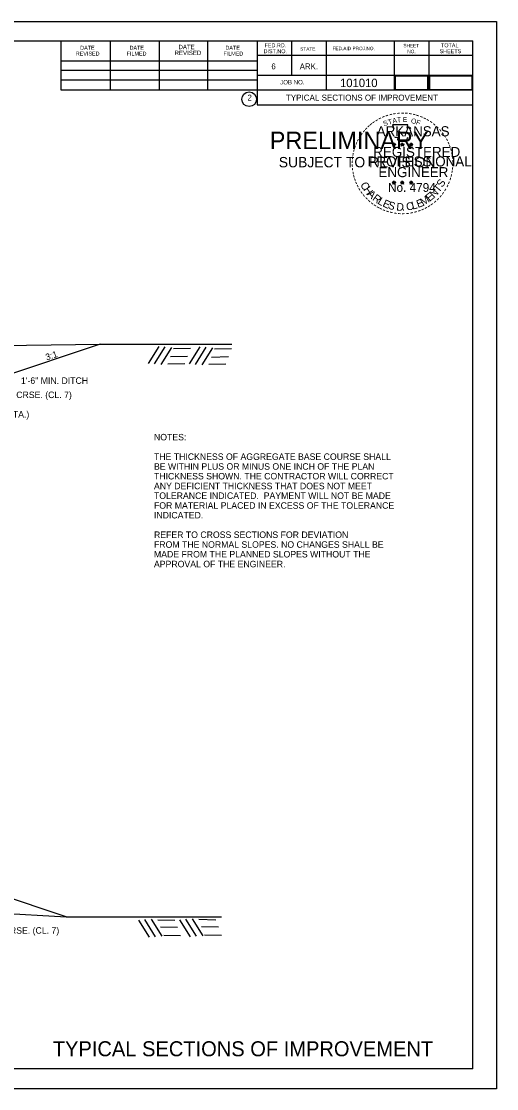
# Model space of a CAD drawing. Extents: x 1373719 to 1374161, y 379835 to 380167.
# Drawn here: x 1373998.9 to 1374046.4, y 379901.1 to 380007.8 of the extents above; entities that cross this region are included whole.
import ezdxf

# ---------------------------------------------------------------- set-up
doc = ezdxf.new("R2010")
doc.units = 0
for name, color, linetype in [('Agg Base Course Text', 7, 'Continuous'), ('DATE', 7, 'Continuous'), ('GREEN_TXT', 7, 'Continuous'), ('Ground Hatch', 7, 'Continuous'), ('Page Number', 7, 'Continuous'), ('R_Border Notes', 7, 'Continuous'), ('R_Border Prem', 7, 'Continuous'), ('R_NoPlot', 7, 'Continuous'), ('R_Stamp', 7, 'Continuous'), ('T_Drafting', 7, 'Continuous'), ('Total Pages', 7, 'Continuous')]:
    doc.layers.add(name, color=color, linetype=linetype)

msp = doc.modelspace()

# ---------------------------------------------------------------- linework, layer by layer
for p, q in [((1374006.82, 379975.49), (1373996.85, 379972.17)), ((1374003.43, 379918.28), (1373993.52, 379921.58))]:
    msp.add_line(p, q)
at = {"layer": 'DATE'}
for p, q in [((1373885.97, 380005.81), (1374044.06, 380005.81)), ((1374002.93, 380000.87), (1374002.93, 380005.81)), ((1374007.86, 380000.87), (1374007.86, 380005.71)), ((1374012.74, 380000.87), (1374012.74, 380005.71)), ((1374017.58, 380000.87), (1374017.58, 380005.71)), ((1374022.51, 380005.81), (1374022.51, 379999.41)), ((1374025.93, 380005.81), (1374025.93, 380002.34)), ((1374029.4, 380005.81), (1374029.4, 380000.87)), ((1374036.19, 380005.81), (1374036.19, 380000.87)), ((1374039.66, 380005.81), (1374039.66, 380000.87)), ((1374044.06, 379903.08), (1374044.06, 380005.81)), ((1374002.93, 380003.8), (1374022.51, 380003.8)), ((1374044.06, 380004.34), (1374022.51, 380004.34)), ((1374044.06, 380004.35), (1374044.06, 380004.35)), ((1374002.93, 380002.87), (1374022.51, 380002.87)), ((1374044.06, 380002.34), (1374022.51, 380002.34)), ((1374002.93, 380001.9), (1374022.51, 380001.9)), ((1374044.06, 380000.87), (1374002.93, 380000.87)), ((1374022.51, 379999.41), (1374044.06, 379999.41)), ((1374044.06, 379903.08), (1373885.97, 379903.08))]:
    msp.add_line(p, q, dxfattribs=at)
msp.add_circle((1374021.71, 379999.98), 0.733, dxfattribs=at)
at = {"layer": 'Ground Hatch'}
for p, q in [((1374011.66, 379973.57), (1374012.72, 379975.28)), ((1374012.26, 379973.52), (1374013.32, 379975.23)), ((1374012.92, 379973.47), (1374013.99, 379975.18)), ((1374014.16, 379975.06), (1374015.86, 379975.11)), ((1374015.75, 379973.53), (1374016.81, 379975.24)), ((1374016.35, 379973.48), (1374017.41, 379975.19)), ((1374017.02, 379973.44), (1374018.08, 379975.14)), ((1374018.25, 379975.03), (1374019.95, 379975.07)), ((1374013.59, 379973.53), (1374015.29, 379973.57)), ((1374013.86, 379974.25), (1374015.55, 379974.29)), ((1374017.68, 379973.49), (1374019.38, 379973.53)), ((1374017.95, 379974.21), (1374019.65, 379974.25)), ((1374011.93, 379918.03), (1374013, 379916.32)), ((1374015.35, 379918.02), (1374016.42, 379916.32)), ((1374016.02, 379918.07), (1374017.09, 379916.36)), ((1374016.69, 379918.02), (1374018.38, 379917.97)), ((1374010.66, 379917.94), (1374011.73, 379916.23)), ((1374011.26, 379917.99), (1374012.33, 379916.28)), ((1374012.59, 379917.98), (1374014.29, 379917.93)), ((1374012.86, 379917.26), (1374014.56, 379917.22)), ((1374014.75, 379917.97), (1374015.82, 379916.27)), ((1374016.95, 379917.3), (1374018.65, 379917.25)), ((1374013.17, 379916.44), (1374014.86, 379916.4)), ((1374017.26, 379916.48), (1374018.95, 379916.44))]:
    msp.add_line(p, q, dxfattribs=at)
at = {"layer": 'Page Number'}
msp.add_lwpolyline([(1374036.3, 380000.95), (1374039.56, 380000.95), (1374039.56, 380002.27), (1374036.3, 380002.27)], close=True, dxfattribs=at)
at = {"layer": 'R_NoPlot'}
msp.add_lwpolyline([(1373879.77, 380007.76), (1374046.44, 380007.76), (1374046.44, 379901.09), (1373879.77, 379901.09)], close=True, dxfattribs=at)
at = {"layer": 'R_Stamp'}
for p, q in [((1374036, 379995.49), (1374036.18, 379995.43)), ((1374036, 379995.49), (1374036.13, 379995.47)), ((1374036, 379995.49), (1374036.12, 379995.43)), ((1374036.07, 379995.28), (1374036.18, 379995.43)), ((1374036.07, 379995.28), (1374036.13, 379995.41)), ((1374036.07, 379995.28), (1374036.18, 379995.39)), ((1374036.18, 379995.62), (1374036.16, 379995.49)), ((1374036.18, 379995.43), (1374036.18, 379995.62)), ((1374036.18, 379995.62), (1374036.2, 379995.49)), ((1374036.35, 379995.49), (1374036.18, 379995.43)), ((1374036.28, 379995.28), (1374036.18, 379995.43)), ((1374036.28, 379995.28), (1374036.18, 379995.39)), ((1374036.35, 379995.49), (1374036.21, 379995.46)), ((1374036.28, 379995.28), (1374036.22, 379995.43)), ((1374036.35, 379995.49), (1374036.25, 379995.44)), ((1374036.84, 379995.49), (1374037.01, 379995.43)), ((1374036.84, 379995.49), (1374036.96, 379995.47)), ((1374036.84, 379995.49), (1374036.96, 379995.43)), ((1374036.9, 379995.28), (1374037.01, 379995.43)), ((1374036.9, 379995.28), (1374036.97, 379995.41)), ((1374036.9, 379995.28), (1374037.01, 379995.39)), ((1374037.01, 379995.62), (1374036.99, 379995.49)), ((1374037.01, 379995.43), (1374037.01, 379995.62)), ((1374037.01, 379995.62), (1374037.04, 379995.49)), ((1374037.19, 379995.49), (1374037.01, 379995.43)), ((1374037.12, 379995.28), (1374037.01, 379995.43)), ((1374037.12, 379995.28), (1374037.01, 379995.39)), ((1374037.19, 379995.49), (1374037.04, 379995.46)), ((1374037.12, 379995.28), (1374037.05, 379995.43)), ((1374037.19, 379995.49), (1374037.08, 379995.44)), ((1374037.72, 379995.48), (1374037.89, 379995.43)), ((1374037.72, 379995.48), (1374037.85, 379995.46)), ((1374037.72, 379995.48), (1374037.84, 379995.42)), ((1374037.79, 379995.28), (1374037.89, 379995.43)), ((1374037.79, 379995.28), (1374037.85, 379995.4)), ((1374037.79, 379995.28), (1374037.89, 379995.39)), ((1374037.89, 379995.61), (1374037.87, 379995.48)), ((1374037.89, 379995.43), (1374037.89, 379995.61)), ((1374037.89, 379995.61), (1374037.92, 379995.48)), ((1374038.07, 379995.48), (1374037.89, 379995.43)), ((1374038, 379995.28), (1374037.89, 379995.43)), ((1374038, 379995.28), (1374037.89, 379995.39)), ((1374038.07, 379995.48), (1374037.93, 379995.46)), ((1374038, 379995.28), (1374037.93, 379995.42)), ((1374038.07, 379995.48), (1374037.97, 379995.43)), ((1374036, 379991.7), (1374036.18, 379991.65)), ((1374036, 379991.7), (1374036.13, 379991.68)), ((1374036, 379991.7), (1374036.12, 379991.64)), ((1374036.07, 379991.5), (1374036.18, 379991.65)), ((1374036.07, 379991.5), (1374036.13, 379991.62)), ((1374036.07, 379991.5), (1374036.17, 379991.61)), ((1374036.18, 379991.83), (1374036.16, 379991.7)), ((1374036.28, 379991.5), (1374036.17, 379991.61)), ((1374036.18, 379991.65), (1374036.18, 379991.83)), ((1374036.18, 379991.83), (1374036.2, 379991.7)), ((1374036.35, 379991.7), (1374036.18, 379991.65)), ((1374036.28, 379991.5), (1374036.18, 379991.65)), ((1374036.35, 379991.7), (1374036.21, 379991.68)), ((1374036.28, 379991.5), (1374036.21, 379991.64)), ((1374036.35, 379991.7), (1374036.25, 379991.65)), ((1374036.84, 379991.7), (1374037.01, 379991.65)), ((1374036.84, 379991.7), (1374036.96, 379991.68)), ((1374036.84, 379991.7), (1374036.95, 379991.64)), ((1374036.9, 379991.5), (1374037.01, 379991.65)), ((1374036.9, 379991.5), (1374036.97, 379991.62)), ((1374036.9, 379991.5), (1374037.01, 379991.61)), ((1374037.01, 379991.83), (1374036.99, 379991.7)), ((1374037.01, 379991.65), (1374037.01, 379991.83)), ((1374037.01, 379991.83), (1374037.03, 379991.7)), ((1374037.18, 379991.7), (1374037.01, 379991.65)), ((1374037.12, 379991.5), (1374037.01, 379991.65)), ((1374037.12, 379991.5), (1374037.01, 379991.61)), ((1374037.18, 379991.7), (1374037.04, 379991.68)), ((1374037.12, 379991.5), (1374037.05, 379991.64)), ((1374037.18, 379991.7), (1374037.08, 379991.65)), ((1374037.72, 379991.7), (1374037.89, 379991.64)), ((1374037.72, 379991.7), (1374037.85, 379991.67)), ((1374037.72, 379991.7), (1374037.84, 379991.64)), ((1374037.79, 379991.49), (1374037.89, 379991.64)), ((1374037.79, 379991.49), (1374037.85, 379991.62)), ((1374037.79, 379991.49), (1374037.89, 379991.6)), ((1374037.89, 379991.82), (1374037.87, 379991.7)), ((1374037.89, 379991.64), (1374037.89, 379991.82)), ((1374037.89, 379991.82), (1374037.92, 379991.7)), ((1374038.07, 379991.7), (1374037.89, 379991.64)), ((1374038, 379991.49), (1374037.89, 379991.64)), ((1374038, 379991.49), (1374037.89, 379991.6)), ((1374038.07, 379991.7), (1374037.92, 379991.67)), ((1374038, 379991.49), (1374037.93, 379991.64)), ((1374038.07, 379991.7), (1374037.97, 379991.65))]:
    msp.add_line(p, q, dxfattribs=at)
for points in [[(1374036.02, 379997.43), (1374036.16, 379997.01)], [(1374037.78, 379996.97), (1374037.85, 379997.11), (1374037.51, 379997.1), (1374037.58, 379997.43), (1374036.02, 379997.43)], [(1374036.27, 379996.22), (1374036.27, 379996.17), (1374036.55, 379996.16), (1374036.52, 379995.93), (1374037.46, 379995.93), (1374037.56, 379996.19)], [(1374036.18, 379995.62), (1374036.28, 379995.28), (1374036, 379995.49), (1374036.35, 379995.49), (1374036.07, 379995.28), (1374036.18, 379995.62)], [(1374037.01, 379995.62), (1374037.12, 379995.28), (1374036.84, 379995.49), (1374037.19, 379995.49), (1374036.9, 379995.28), (1374037.01, 379995.62)], [(1374037.89, 379995.61), (1374038, 379995.28), (1374037.72, 379995.48), (1374038.07, 379995.48), (1374037.79, 379995.28), (1374037.89, 379995.61)], [(1374036.18, 379991.83), (1374036.28, 379991.5), (1374036, 379991.7), (1374036.35, 379991.7), (1374036.07, 379991.5), (1374036.18, 379991.83)], [(1374037.01, 379991.83), (1374037.12, 379991.5), (1374036.84, 379991.7), (1374037.18, 379991.7), (1374036.9, 379991.5), (1374037.01, 379991.83)], [(1374037.89, 379991.82), (1374038, 379991.49), (1374037.72, 379991.7), (1374038.07, 379991.7), (1374037.79, 379991.49), (1374037.89, 379991.82)]]:
    msp.add_lwpolyline(points, dxfattribs=at)
for centre, radius in [((1374036.18, 379995.43), 0.0861), ((1374036.18, 379995.43), 0.0723), ((1374036.18, 379995.43), 0.0579), ((1374036.18, 379995.43), 0.0495), ((1374036.18, 379995.43), 0.0374), ((1374036.18, 379995.43), 0.0248), ((1374036.18, 379995.43), 0.0148), ((1374037.01, 379995.43), 0.0861), ((1374037.01, 379995.43), 0.0723), ((1374037.01, 379995.43), 0.0579), ((1374037.01, 379995.43), 0.0495), ((1374037.01, 379995.43), 0.0374), ((1374037.01, 379995.43), 0.0248), ((1374037.01, 379995.43), 0.0148), ((1374037.89, 379995.43), 0.0861), ((1374037.89, 379995.43), 0.0723), ((1374037.89, 379995.43), 0.0579), ((1374037.89, 379995.43), 0.0495), ((1374037.89, 379995.43), 0.0374), ((1374037.89, 379995.43), 0.0248), ((1374037.89, 379995.43), 0.0148), ((1374036.18, 379991.65), 0.0861), ((1374036.18, 379991.65), 0.0723), ((1374036.18, 379991.65), 0.0579), ((1374036.18, 379991.65), 0.0495), ((1374036.18, 379991.65), 0.0374), ((1374036.18, 379991.65), 0.0248), ((1374036.18, 379991.65), 0.0148), ((1374037.01, 379991.65), 0.0861), ((1374037.01, 379991.65), 0.0723), ((1374037.01, 379991.65), 0.0579), ((1374037.01, 379991.65), 0.0495), ((1374037.01, 379991.65), 0.0374), ((1374037.01, 379991.65), 0.0248), ((1374037.01, 379991.65), 0.0148), ((1374037.89, 379991.64), 0.0861), ((1374037.89, 379991.64), 0.0723), ((1374037.89, 379991.64), 0.0579), ((1374037.89, 379991.64), 0.0495), ((1374037.89, 379991.64), 0.0374), ((1374037.89, 379991.64), 0.0248), ((1374037.89, 379991.64), 0.0148)]:
    msp.add_circle(centre, radius, dxfattribs=at)
at = {"layer": 'T_Drafting'}
for points in [[(1373907.35, 379968.92), (1373923.89, 379968.85), (1373942.81, 379971.02), (1373964.3, 379972.17), (1373992.08, 379975.29), (1374006.82, 379975.49), (1374019.98, 379975.49)], [(1373909.63, 379921.87), (1373922.47, 379921.8), (1373942.6, 379919.02), (1373967.06, 379919.64), (1373996.43, 379918.66), (1374003.43, 379918.28), (1374018.95, 379918.28)]]:
    msp.add_lwpolyline(points, dxfattribs=at)
at = {"layer": 'Total Pages'}
msp.add_lwpolyline([(1374039.74, 380000.95), (1374043.98, 380000.95), (1374043.98, 380002.27), (1374039.74, 380002.27)], close=True, dxfattribs=at)

# ---------------------------------------------------------------- texts
at = {"layer": 'Agg Base Course Text'}
for s, p in [('AGGREGATE BASE CRSE. (CL. 7)', (1373990.13, 379970.11)), ('(24.00 TONS PER STA.)', (1373990.13, 379968.16)), ('AGGREGATE BASE CRSE. (CL. 7)', (1373988.87, 379916.58))]:
    msp.add_text(s, height=0.65, dxfattribs=at).set_placement(p)
at = {"layer": 'DATE'}
for s, height, p in [('FED.RD.', 0.391, (1374023.25, 380005.17)), ('SHEET', 0.342, (1374037.12, 380005.17)), ('TOTAL', 0.391, (1374040.88, 380005.17)), ('REVISED', 0.391, (1374004.39, 380004.34)), ('DATE', 0.391, (1374004.83, 380004.93)), ('FILMED', 0.391, (1374009.47, 380004.34)), ('DATE', 0.391, (1374009.76, 380004.93)), ('REVISED', 0.44, (1374014.26, 380004.39)), ('DATE', 0.44, (1374014.65, 380004.98)), ('FILMED', 0.391, (1374019.14, 380004.34)), ('DATE', 0.391, (1374019.34, 380004.93)), ('DIST.NO.', 0.391, (1374023.15, 380004.58)), ('STATE', 0.342, (1374026.81, 380004.83)), ('FED.AID PROJ.NO.', 0.342, (1374030.04, 380004.88)), ('NO.', 0.342, (1374037.51, 380004.58)), ('SHEETS', 0.391, (1374040.74, 380004.58)), ('6', 0.586, (1374023.93, 380002.97)), ('ARK.', 0.586, (1374026.76, 380002.97)), ('JOB NO.', 0.44, (1374024.81, 380001.46)), ('2', 0.586, (1374021.54, 379999.85)), ('TYPICAL SECTIONS OF IMPROVEMENT', 1.5, (1374002.09, 379904.33))]:
    msp.add_text(s, height=height, dxfattribs=at).set_placement(p)
at = {"layer": 'GREEN_TXT'}
msp.add_text('3:1', height=0.65, rotation=18.4349, dxfattribs=at).set_placement((1374001.48, 379973.86))
for s, p in [('1\'-6" MIN. DITCH', (1373998.91, 379971.53)), ('NOTES: ', (1374012.2, 379965.88)), ('THE THICKNESS OF AGGREGATE BASE COURSE SHALL', (1374012.2, 379963.93)), ('BE WITHIN PLUS OR MINUS ONE INCH OF THE PLAN', (1374012.2, 379962.95)), ('THICKNESS SHOWN. THE CONTRACTOR WILL CORRECT', (1374012.2, 379961.98)), ('ANY DEFICIENT THICKNESS THAT DOES NOT MEET', (1374012.2, 379961)), ('TOLERANCE INDICATED.  PAYMENT WILL NOT BE MADE', (1374012.2, 379960.03)), ('FOR MATERIAL PLACED IN EXCESS OF THE TOLERANCE', (1374012.2, 379959.05)), ('INDICATED.', (1374012.2, 379958.08)), ('REFER TO CROSS SECTIONS FOR DEVIATION', (1374012.2, 379956.13)), ('FROM THE NORMAL SLOPES. NO CHANGES SHALL BE', (1374012.2, 379955.15)), ('MADE FROM THE PLANNED SLOPES WITHOUT THE ', (1374012.2, 379954.18)), ('APPROVAL OF THE ENGINEER.    ', (1374012.2, 379953.2))]:
    msp.add_text(s, height=0.65, dxfattribs=at).set_placement(p)
at = {"layer": 'R_Border Notes'}
for s, height, p in [('101010', 0.84, (1374030.79, 380001.19)), ('TYPICAL SECTIONS OF IMPROVEMENT', 0.6, (1374025.38, 379999.84))]:
    msp.add_text(s, height=height, dxfattribs=at).set_placement(p)
at = {"layer": 'R_Border Prem'}
for s, height, p in [('PRELIMINARY', 1.75, (1374023.77, 379994.99)), ('SUBJECT TO REVISION', 1.0376, (1374024.67, 379993.17))]:
    msp.add_text(s, height=height, dxfattribs=at).set_placement(p)
at = {"layer": 'R_Stamp'}
for s, height, rotation, p in [('-', 0.8, 28.7918, (1374034.76, 379997.7)), ('-', 0.8, 24.3072, (1374035.08, 379997.86)), ('-', 0.8, 19.1761, (1374035.4, 379997.99)), ('T', 0.5, 16.4036, (1374035.66, 379997.43)), ('-', 0.8, 13.6302, (1374035.77, 379998.11)), ('A', 0.5, 11.2132, (1374036.07, 379997.56)), ('-', 0.8, 10.2193, (1374036.11, 379998.19)), ('T', 0.5, 6.0228, (1374036.5, 379997.64)), ('-', 0.8, 5.8968, (1374036.48, 379998.25)), ('-', 0.8, 0.1862, (1374036.86, 379998.28)), ('E', 0.5, 0.8323, (1374037.05, 379997.7)), ('-', 0.8, 357.743, (1374037.22, 379998.28)), ('-', 0.8, 352.1617, (1374037.6, 379998.25)), ('O', 0.5, 350.4515, (1374037.85, 379997.59)), ('-', 0.8, 347.2049, (1374037.96, 379998.19)), ('-', 0.8, 342.3362, (1374038.27, 379998.11)), ('-', 0.8, 337.8551, (1374038.64, 379998)), ('-', 0.8, 334.1211, (1374038.96, 379997.87)), ('-', 0.8, 329.6409, (1374039.25, 379997.73)), ('-', 0.8, 48.4231, (1374033.5, 379996.68)), ('-', 0.8, 42.9622, (1374033.72, 379996.92)), ('-', 0.8, 38.9507, (1374033.94, 379997.13)), ('-', 0.8, 36.2317, (1374034.18, 379997.32)), ('-', 0.8, 34.0636, (1374034.47, 379997.51)), ('S', 0.5, 21.594, (1374035.2, 379997.27)), ('F', 0.5, 340.0707, (1374038.33, 379997.48)), ('-', 0.8, 325.8627, (1374039.57, 379997.55)), ('-', 0.8, 320.5297, (1374039.87, 379997.33)), ('-', 0.8, 315.5786, (1374040.17, 379997.09)), ('-', 0.8, 309.8797, (1374040.46, 379996.81)), ('-', 0.8, 62.8713, (1374032.77, 379995.58)), ('-', 0.8, 58.0706, (1374032.93, 379995.89)), ('-', 0.8, 54.2325, (1374033.09, 379996.15)), ('-', 0.8, 50.6142, (1374033.3, 379996.44)), ('-', 0.8, 306.6522, (1374040.72, 379996.51)), ('-', 0.7, 303.6753, (1374040.96, 379996.23)), ('-', 0.8, 299.6684, (1374041.12, 379995.93)), ('-', 0.8, 75.461, (1374032.43, 379994.6)), ('-', 0.8, 72.3945, (1374032.53, 379994.96)), ('-', 0.8, 67.7743, (1374032.64, 379995.28)), ('-', 0.8, 294.6628, (1374041.28, 379995.62)), ('-', 0.8, 290.5728, (1374041.41, 379995.33)), ('-', 0.8, 285.1233, (1374041.53, 379995.04)), ('-', 0.8, 89.0622, (1374032.32, 379993.55)), ('-', 0.8, 85.1863, (1374032.33, 379993.9)), ('-', 0.8, 81.2013, (1374032.37, 379994.25)), ('-', 0.8, 280.5493, (1374041.63, 379994.67)), ('-', 0.8, 276.5962, (1374041.71, 379994.29)), ('-', 0.8, 274.3301, (1374041.74, 379993.92)), ('-', 0.8, 94.1959, (1374032.33, 379993.19)), ('-', 0.8, 98.9479, (1374032.37, 379992.86)), ('-', 0.8, 101.7149, (1374032.44, 379992.49)), ('-', 0.8, 260.9953, (1374041.71, 379992.95)), ('-', 0.8, 263.5172, (1374041.75, 379993.28)), ('-', 0.8, 269.9407, (1374041.76, 379993.61)), ('-', 0.8, 105.4578, (1374032.52, 379992.19)), ('-', 0.8, 109.0874, (1374032.63, 379991.88)), ('-', 0.8, 114.0643, (1374032.75, 379991.58)), ('C', 0.77, 296.9133, (1374032.79, 379991.47)), ('S', 0.77, 57.878, (1374041.02, 379991.11)), ('-', 0.8, 247.8887, (1374041.45, 379991.91)), ('-', 0.8, 255.7626, (1374041.56, 379992.27)), ('-', 0.8, 255.7626, (1374041.66, 379992.61)), ('-', 0.8, 115.7289, (1374032.91, 379991.27)), ('-', 0.8, 120.4471, (1374033.08, 379990.98)), ('-', 0.8, 125.8934, (1374033.29, 379990.7)), ('H', 0.77, 303.2799, (1374033.09, 379990.95)), ('A', 0.77, 316.013, (1374033.45, 379990.44)), ('E', 0.77, 38.7783, (1374039.73, 379989.71)), ('N', 0.77, 45.1449, (1374040.18, 379990.07)), ('T', 0.77, 51.5114, (1374040.66, 379990.59)), ('-', 0.8, 233.8452, (1374040.93, 379990.9)), ('-', 0.8, 239.0712, (1374041.13, 379991.22)), ('-', 0.8, 244.6197, (1374041.32, 379991.6)), ('-', 0.8, 130.7181, (1374033.52, 379990.42)), ('-', 0.8, 134.2238, (1374033.78, 379990.15)), ('-', 0.8, 138.9338, (1374034.04, 379989.92)), ('-', 0.8, 144.6463, (1374034.32, 379989.71)), ('R', 0.77, 322.3796, (1374033.96, 379989.95)), ('-', 0.8, 148.0898, (1374034.6, 379989.53)), ('L', 0.77, 328.7461, (1374034.48, 379989.58)), ('E', 0.77, 335.1127, (1374034.98, 379989.3)), ('S', 0.77, 341.4792, (1374035.51, 379989.08)), ('D', 0.77, 354.2124, (1374036.39, 379988.87)), ('C', 0.77, 6.9455, (1374037.44, 379988.86)), ('L', 0.77, 13.3121, (1374038.03, 379988.95)), ('E', 0.77, 19.6786, (1374038.58, 379989.11)), ('M', 0.77, 32.4117, (1374039.09, 379989.3)), ('-', 0.8, 215.7363, (1374039.94, 379989.84)), ('-', 0.8, 221.0851, (1374040.21, 379990.08)), ('-', 0.8, 225.7653, (1374040.47, 379990.33)), ('-', 0.8, 231.2538, (1374040.71, 379990.61)), ('-', 0.8, 151.5704, (1374034.89, 379989.36)), ('-', 0.8, 154.6002, (1374035.15, 379989.24)), ('-', 0.8, 158.5612, (1374035.46, 379989.11)), ('-', 0.8, 162.7983, (1374035.8, 379989.01)), ('-', 0.8, 167.5555, (1374036.16, 379988.93)), ('-', 0.8, 173.1155, (1374036.55, 379988.87)), ('-', 0.8, 176.5183, (1374036.92, 379988.84)), ('-', 0.8, 181.5918, (1374037.29, 379988.85)), ('.', 0.77, 0.5789, (1374036.98, 379988.84)), ('-', 0.8, 185.8167, (1374037.7, 379988.89)), ('-', 0.8, 191.2858, (1374038.06, 379988.96)), ('-', 0.8, 195.4743, (1374038.43, 379989.06)), ('-', 0.8, 200.7184, (1374038.77, 379989.18)), ('-', 0.8, 204.2516, (1374039.08, 379989.31)), ('-', 0.8, 207.3568, (1374039.39, 379989.47)), ('-', 0.8, 212.2491, (1374039.67, 379989.65))]:
    msp.add_text(s, height=height, rotation=rotation, dxfattribs=at).set_placement(p)
for s, height, p in [('ARKANSAS', 1, (1374034.45, 379996.28)), ('REGISTERED', 1, (1374034.11, 379994.21)), ('PROFESSIONAL', 1, (1374033.54, 379993.26)), ('ENGINEER', 1, (1374034.63, 379992.19)), ('No. 4794', 0.878, (1374035.59, 379990.72))]:
    msp.add_text(s, height=height, dxfattribs=at).set_placement(p)

doc.saveas('drawing.dxf')
